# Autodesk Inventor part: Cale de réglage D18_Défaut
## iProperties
Shininess: 64.0
Length Units: 11269
Angle Units: 11279
Time Units: 11290
Mass Units: 11283
Length Display Precision: 3
Angle Display Precision: 2
Compacted: True
Part Number: Cale de réglage D18_Défaut
Document SubType Name: Modeling
Created: 2006-01
Material: Par défaut
Designer: Fricot
Density: 0.0
Volumn: 0.0
Area: 0.0
PropertySet Name: Model Information
Control State: 0
Master: False
Checked Out: False
Author: Fricot
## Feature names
1. Base1
